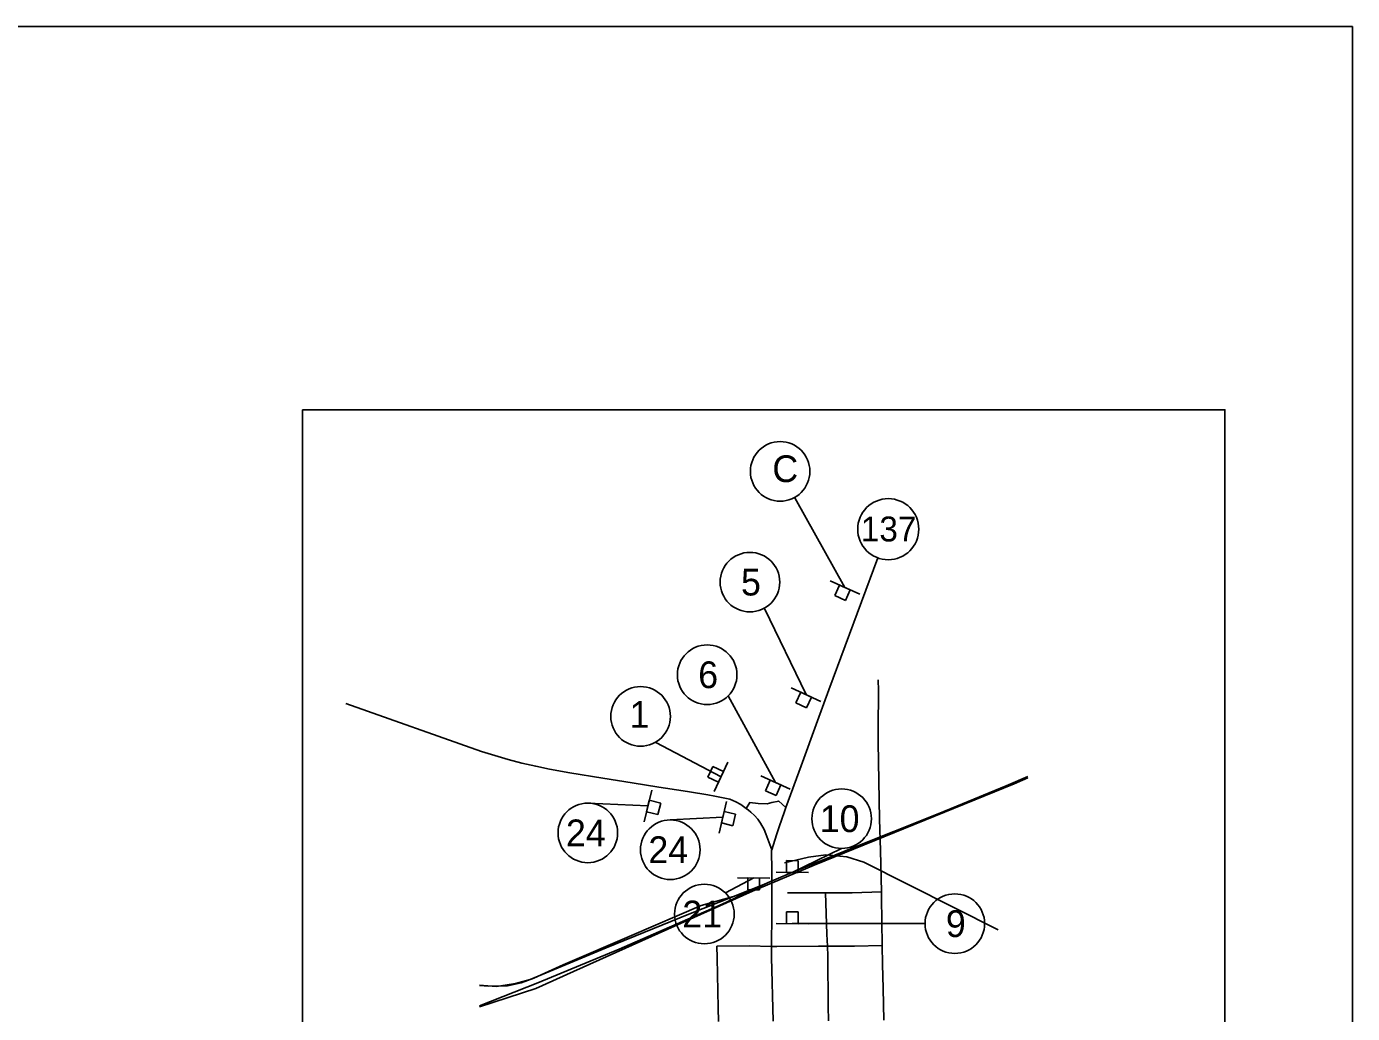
# Model space of a CAD drawing. Extents: x 10133 to 81668, y 5524 to 11018.
# Drawn here: x 15963 to 16868, y 9270 to 9944 of the extents above; entities that cross this region are included whole.
import ezdxf

# ---------------------------------------------------------------- set-up
doc = ezdxf.new("R2010")
doc.units = 0
for name, color, linetype in [('Default', 7, 'Continuous'), ('DisBoundDim', 7, 'Continuous'), ('DisCLMLOR', 7, 'Continuous'), ('DisCLMLSUR', 7, 'Continuous'), ('dsnShtPlotShapeBatchPrint', 7, 'Continuous'), ('Level 3', 7, 'Continuous'), ('trf_Signal_(Temp)_Layout', 7, 'Continuous'), ('trf_SignNumber_Text', 7, 'Continuous')]:
    doc.layers.add(name, color=color, linetype=linetype)

msp = doc.modelspace()

# ---------------------------------------------------------------- linework, layer by layer
at = {"layer": 'Default'}
for points in [[(16543.77, 9498.06), (16544.17, 9490.88), (16543.96, 9464.55), (16543.96, 9464.55)], [(16453.71, 9410.28), (16450.13, 9412.93), (16446.83, 9414.78), (16442.72, 9416.56), (16432.33, 9418.64), (16427.57, 9419.58), (16415.16, 9421.56), (16410.73, 9422.27), (16394.12, 9424.91), (16376.07, 9427.79), (16355.95, 9431.06), (16333.49, 9434.72), (16319.65, 9437.21), (16310.21, 9439.09), (16300.83, 9441.24), (16291.52, 9443.66), (16282.28, 9446.34), (16273.12, 9449.28), (16180.69, 9481.91)], [(16546.08, 9353.48), (16545.58, 9381.67), (16544.73, 9402.89), (16543.89, 9455.23), (16543.96, 9464.55)], [(16271.9, 9274.92), (16310.35, 9287.49), (16336.01, 9298.98), (16458.1, 9353.77), (16500.24, 9371.53), (16636.66, 9427.09), (16646.09, 9431.12)], [(16468.47, 9359.56), (16483.49, 9365.8), (16500.75, 9372.98), (16509.39, 9376.46), (16525.56, 9382.98), (16584.78, 9406.61), (16597.46, 9411.78), (16631.13, 9425.78), (16646.09, 9432)], [(16471.24, 9382.11), (16467.29, 9392.94), (16466.19, 9395.96), (16463.5, 9400.29), (16461.8, 9403.03), (16459.52, 9405.45), (16457.08, 9407.7), (16455.3, 9409.14), (16453.71, 9410.28)], [(16472.21, 9265.05), (16471, 9308.81), (16471.08, 9316.09), (16471.33, 9338.83), (16471.42, 9347.43), (16471.26, 9367.38), (16471.14, 9381.81), (16471.24, 9382.11)], [(16479.96, 9373.17), (16496.37, 9377.06), (16508.21, 9378.53), (16522.45, 9377.16), (16534.08, 9373.6), (16625.81, 9327.4)], [(16271.9, 9289.57), (16283.24, 9288.79), (16289.44, 9289.71), (16296.38, 9290.73), (16306.32, 9293.47), (16358.29, 9315.18), (16390.1, 9328.12), (16414.66, 9338.11), (16465.83, 9358.47), (16468.47, 9359.56)], [(16271.9, 9275.62), (16311.74, 9291.25), (16367.23, 9314.25), (16437.46, 9344.93), (16468.47, 9359.56)], [(16458.1, 9353.77), (16423.1, 9343.97), (16375.67, 9323.48), (16329.05, 9303.57), (16308.88, 9294.4), (16300.32, 9291.17), (16290.92, 9289.26), (16278.04, 9288.93), (16271.9, 9289.49)], [(16482.07, 9352.65), (16508.02, 9352.73)], [(16508.02, 9352.73), (16526.21, 9352.79), (16546.08, 9353.48)], [(16509.32, 9316.37), (16508.94, 9324.42), (16508.02, 9352.73)], [(16546.66, 9316.69), (16546.15, 9349.55), (16546.08, 9353.48)], [(16433.89, 9316.19), (16455.81, 9316.54), (16471.06, 9316.09), (16474.76, 9315.98), (16503.2, 9316.4), (16509.32, 9316.37)], [(16434.84, 9264.84), (16434.67, 9274.29), (16433.96, 9308.38), (16433.89, 9316.19)], [(16509.32, 9316.37), (16527.81, 9316.26), (16546.66, 9316.69)], [(16510.01, 9265.38), (16509.79, 9275.33), (16509.65, 9309.42), (16509.32, 9316.37)], [(16547.84, 9265.77), (16547.84, 9265.77), (16547.29, 9287.29), (16546.86, 9304), (16546.66, 9316.69)]]:
    msp.add_lwpolyline(points, dxfattribs=at)
msp.add_circle((16550.76, 9600.92), 20.85, dxfattribs=at)
at = {"layer": 'DisBoundDim'}
for p, q in [((16531.31, 9556.54), (16511.19, 9565.75)), ((16517.61, 9562.81), (16514.28, 9555.54)), ((16521.55, 9552.2), (16514.28, 9555.54)), ((16524.88, 9559.48), (16521.55, 9552.2)), ((16504.71, 9483.38), (16484.59, 9492.59)), ((16491.01, 9489.65), (16487.68, 9482.38)), ((16494.96, 9479.05), (16487.68, 9482.38)), ((16498.29, 9486.32), (16494.96, 9479.05)), ((16427.75, 9431.61), (16431.08, 9438.88)), ((16438.35, 9435.55), (16431.08, 9438.88)), ((16432.08, 9421.85), (16441.29, 9441.98)), ((16435.02, 9428.28), (16427.75, 9431.61)), ((16483.94, 9423.42), (16463.82, 9432.63)), ((16470.25, 9429.69), (16466.91, 9422.42)), ((16389.38, 9422.74), (16384.21, 9401.22)), ((16474.19, 9419.09), (16466.91, 9422.42)), ((16477.52, 9426.36), (16474.19, 9419.09)), ((16387.73, 9415.87), (16395.51, 9414)), ((16395.51, 9414), (16393.64, 9406.22)), ((16440.5, 9415.04), (16435.33, 9393.52)), ((16385.86, 9408.09), (16393.64, 9406.22)), ((16438.85, 9408.17), (16446.63, 9406.3)), ((16446.63, 9406.3), (16444.76, 9398.52)), ((16436.98, 9400.39), (16444.76, 9398.52)), ((16481.26, 9366.69), (16481.32, 9374.69)), ((16481.32, 9374.69), (16489.32, 9374.64)), ((16489.26, 9366.64), (16489.32, 9374.64)), ((16474.19, 9366.74), (16496.33, 9366.59)), ((16470.04, 9362.79), (16447.91, 9362.87)), ((16454.97, 9362.84), (16454.94, 9354.84)), ((16462.97, 9362.81), (16462.94, 9354.81)), ((16462.94, 9354.81), (16454.94, 9354.84)), ((16481.26, 9331.69), (16481.32, 9339.69)), ((16481.32, 9339.69), (16489.32, 9339.64)), ((16489.26, 9331.64), (16489.32, 9339.64)), ((16474.19, 9331.74), (16496.33, 9331.59))]:
    msp.add_line(p, q, dxfattribs=at)
at = {"layer": 'DisCLMLOR'}
for p, q in [((16514.28, 9555.54), (16517.61, 9562.81)), ((16514.28, 9555.54), (16517.61, 9562.81)), ((16514.28, 9555.54), (16517.61, 9562.81)), ((16514.28, 9555.54), (16517.61, 9562.81)), ((16521.55, 9552.2), (16514.28, 9555.54)), ((16521.55, 9552.2), (16514.28, 9555.54)), ((16521.55, 9552.2), (16514.28, 9555.54)), ((16521.55, 9552.2), (16514.28, 9555.54)), ((16517.61, 9562.81), (16524.88, 9559.48)), ((16517.61, 9562.81), (16524.88, 9559.48)), ((16517.61, 9562.81), (16524.88, 9559.48)), ((16517.61, 9562.81), (16524.88, 9559.48)), ((16524.88, 9559.48), (16521.55, 9552.2)), ((16524.88, 9559.48), (16521.55, 9552.2)), ((16524.88, 9559.48), (16521.55, 9552.2)), ((16524.88, 9559.48), (16521.55, 9552.2)), ((16487.68, 9482.38), (16491.01, 9489.65)), ((16487.68, 9482.38), (16491.01, 9489.65)), ((16487.68, 9482.38), (16491.01, 9489.65)), ((16487.68, 9482.38), (16491.01, 9489.65)), ((16494.96, 9479.05), (16487.68, 9482.38)), ((16494.96, 9479.05), (16487.68, 9482.38)), ((16494.96, 9479.05), (16487.68, 9482.38)), ((16494.96, 9479.05), (16487.68, 9482.38)), ((16491.01, 9489.65), (16498.29, 9486.32)), ((16491.01, 9489.65), (16498.29, 9486.32)), ((16491.01, 9489.65), (16498.29, 9486.32)), ((16491.01, 9489.65), (16498.29, 9486.32)), ((16498.29, 9486.32), (16494.96, 9479.05)), ((16498.29, 9486.32), (16494.96, 9479.05)), ((16498.29, 9486.32), (16494.96, 9479.05)), ((16498.29, 9486.32), (16494.96, 9479.05)), ((16427.75, 9431.61), (16431.08, 9438.88)), ((16427.75, 9431.61), (16431.08, 9438.88)), ((16427.75, 9431.61), (16431.08, 9438.88)), ((16427.75, 9431.61), (16431.08, 9438.88)), ((16431.08, 9438.88), (16438.35, 9435.55)), ((16431.08, 9438.88), (16438.35, 9435.55)), ((16431.08, 9438.88), (16438.35, 9435.55)), ((16431.08, 9438.88), (16438.35, 9435.55)), ((16435.02, 9428.28), (16427.75, 9431.61)), ((16435.02, 9428.28), (16427.75, 9431.61)), ((16435.02, 9428.28), (16427.75, 9431.61)), ((16435.02, 9428.28), (16427.75, 9431.61)), ((16438.35, 9435.55), (16435.02, 9428.28)), ((16438.35, 9435.55), (16435.02, 9428.28)), ((16438.35, 9435.55), (16435.02, 9428.28)), ((16438.35, 9435.55), (16435.02, 9428.28)), ((16466.91, 9422.42), (16470.25, 9429.69)), ((16466.91, 9422.42), (16470.25, 9429.69)), ((16466.91, 9422.42), (16470.25, 9429.69)), ((16466.91, 9422.42), (16470.25, 9429.69)), ((16470.25, 9429.69), (16477.52, 9426.36)), ((16470.25, 9429.69), (16477.52, 9426.36)), ((16470.25, 9429.69), (16477.52, 9426.36)), ((16470.25, 9429.69), (16477.52, 9426.36)), ((16474.19, 9419.09), (16466.91, 9422.42)), ((16474.19, 9419.09), (16466.91, 9422.42)), ((16474.19, 9419.09), (16466.91, 9422.42)), ((16474.19, 9419.09), (16466.91, 9422.42)), ((16477.52, 9426.36), (16474.19, 9419.09)), ((16477.52, 9426.36), (16474.19, 9419.09)), ((16477.52, 9426.36), (16474.19, 9419.09)), ((16477.52, 9426.36), (16474.19, 9419.09)), ((16385.86, 9408.09), (16387.73, 9415.87)), ((16385.86, 9408.09), (16387.73, 9415.87)), ((16385.86, 9408.09), (16387.73, 9415.87)), ((16385.86, 9408.09), (16387.73, 9415.87)), ((16387.73, 9415.87), (16395.51, 9414)), ((16387.73, 9415.87), (16395.51, 9414)), ((16387.73, 9415.87), (16395.51, 9414)), ((16387.73, 9415.87), (16395.51, 9414)), ((16395.51, 9414), (16393.64, 9406.22)), ((16395.51, 9414), (16393.64, 9406.22)), ((16395.51, 9414), (16393.64, 9406.22)), ((16395.51, 9414), (16393.64, 9406.22)), ((16393.64, 9406.22), (16385.86, 9408.09)), ((16393.64, 9406.22), (16385.86, 9408.09)), ((16393.64, 9406.22), (16385.86, 9408.09)), ((16393.64, 9406.22), (16385.86, 9408.09)), ((16436.98, 9400.39), (16438.85, 9408.17)), ((16436.98, 9400.39), (16438.85, 9408.17)), ((16436.98, 9400.39), (16438.85, 9408.17)), ((16436.98, 9400.39), (16438.85, 9408.17)), ((16438.85, 9408.17), (16446.63, 9406.3)), ((16438.85, 9408.17), (16446.63, 9406.3)), ((16438.85, 9408.17), (16446.63, 9406.3)), ((16438.85, 9408.17), (16446.63, 9406.3)), ((16446.63, 9406.3), (16444.76, 9398.52)), ((16446.63, 9406.3), (16444.76, 9398.52)), ((16446.63, 9406.3), (16444.76, 9398.52)), ((16446.63, 9406.3), (16444.76, 9398.52)), ((16444.76, 9398.52), (16436.98, 9400.39)), ((16444.76, 9398.52), (16436.98, 9400.39)), ((16444.76, 9398.52), (16436.98, 9400.39)), ((16444.76, 9398.52), (16436.98, 9400.39)), ((16481.26, 9366.69), (16481.32, 9374.69)), ((16481.26, 9366.69), (16481.32, 9374.69)), ((16481.26, 9366.69), (16481.32, 9374.69)), ((16481.26, 9366.69), (16481.32, 9374.69)), ((16481.32, 9374.69), (16489.32, 9374.64)), ((16481.32, 9374.69), (16489.32, 9374.64)), ((16481.32, 9374.69), (16489.32, 9374.64)), ((16481.32, 9374.69), (16489.32, 9374.64)), ((16489.32, 9374.64), (16489.26, 9366.64)), ((16489.32, 9374.64), (16489.26, 9366.64)), ((16489.32, 9374.64), (16489.26, 9366.64)), ((16489.32, 9374.64), (16489.26, 9366.64)), ((16489.26, 9366.64), (16481.26, 9366.69)), ((16489.26, 9366.64), (16481.26, 9366.69)), ((16489.26, 9366.64), (16481.26, 9366.69)), ((16489.26, 9366.64), (16481.26, 9366.69)), ((16454.94, 9354.84), (16454.97, 9362.84)), ((16454.94, 9354.84), (16454.97, 9362.84)), ((16454.94, 9354.84), (16454.97, 9362.84)), ((16454.94, 9354.84), (16454.97, 9362.84)), ((16454.97, 9362.84), (16462.97, 9362.81)), ((16454.97, 9362.84), (16462.97, 9362.81)), ((16454.97, 9362.84), (16462.97, 9362.81)), ((16454.97, 9362.84), (16462.97, 9362.81)), ((16462.97, 9362.81), (16462.94, 9354.81)), ((16462.97, 9362.81), (16462.94, 9354.81)), ((16462.97, 9362.81), (16462.94, 9354.81)), ((16462.97, 9362.81), (16462.94, 9354.81)), ((16462.94, 9354.81), (16454.94, 9354.84)), ((16462.94, 9354.81), (16454.94, 9354.84)), ((16462.94, 9354.81), (16454.94, 9354.84)), ((16462.94, 9354.81), (16454.94, 9354.84)), ((16481.26, 9331.69), (16481.32, 9339.69)), ((16481.26, 9331.69), (16481.32, 9339.69)), ((16481.26, 9331.69), (16481.32, 9339.69)), ((16481.26, 9331.69), (16481.32, 9339.69)), ((16481.32, 9339.69), (16489.32, 9339.64)), ((16481.32, 9339.69), (16489.32, 9339.64)), ((16481.32, 9339.69), (16489.32, 9339.64)), ((16481.32, 9339.69), (16489.32, 9339.64)), ((16489.32, 9339.64), (16489.26, 9331.64)), ((16489.32, 9339.64), (16489.26, 9331.64)), ((16489.32, 9339.64), (16489.26, 9331.64)), ((16489.32, 9339.64), (16489.26, 9331.64)), ((16489.26, 9331.64), (16481.26, 9331.69)), ((16489.26, 9331.64), (16481.26, 9331.69)), ((16489.26, 9331.64), (16481.26, 9331.69)), ((16489.26, 9331.64), (16481.26, 9331.69))]:
    msp.add_line(p, q, dxfattribs=at)
at = {"layer": 'DisCLMLSUR'}
for p, q in [((16521.25, 9561.14), (16487.03, 9622.32)), ((16494.65, 9487.99), (16466.43, 9546.73)), ((16473.88, 9428.03), (16441.58, 9487.18)), ((16436.69, 9431.91), (16392.18, 9455.3)), ((16386.79, 9411.98), (16345.78, 9413.95)), ((16437.92, 9404.28), (16402.05, 9402.45)), ((16485.26, 9366.67), (16518.96, 9382.97)), ((16458.97, 9362.83), (16439.66, 9352.6)), ((16485.26, 9331.67), (16575.86, 9331.67))]:
    msp.add_line(p, q, dxfattribs=at)
at = {"layer": 'dsnShtPlotShapeBatchPrint'}
for points in [[(16480.91, 9410.99), (16491.37, 9439.39), (16502.51, 9470.04), (16510.19, 9491.17), (16543.67, 9581.35)], [(16453.71, 9410.28), (16456.36, 9414.42), (16462.09, 9413.64), (16468.03, 9413.5), (16471.29, 9414.25), (16476.07, 9415.34), (16480.91, 9410.99)], [(16471.24, 9382.11), (16474.54, 9392.28), (16476.37, 9397.7), (16479.92, 9408.24), (16480.91, 9410.99)]]:
    msp.add_lwpolyline(points, dxfattribs=at)
at = {"layer": 'Level 3'}
msp.add_lwpolyline([(13732.52, 9944.02), (16867.53, 9944.02), (16867.53, 7924.02), (13732.52, 7924.02)], close=True, dxfattribs=at)
at = {"layer": 'trf_Signal_(Temp)_Layout'}
msp.add_lwpolyline([(16151.16, 9682.4), (16780.52, 9682.4), (16780.52, 8361.35), (16151.16, 8361.35)], close=True, dxfattribs=at)
at = {"layer": 'trf_SignNumber_Text'}
for centre in [(16476.99, 9640.37), (16456.39, 9564.78), (16427.2, 9501.55), (16381.78, 9473.14), (16518.96, 9403.3), (16345.78, 9393.62), (16402.05, 9382.12), (16425.29, 9338.23), (16596.19, 9331.67)]:
    msp.add_circle(centre, 20.33, dxfattribs=at)

# ---------------------------------------------------------------- texts
at = {"layer": 'Default'}
msp.add_text('137', height=17, dxfattribs=at).set_placement((16532.06, 9592.54))
at = {"layer": 'trf_SignNumber_Text'}
for s, height, p in [('C', 18.26, (16471.68, 9633.04)), ('5', 18.26, (16450.28, 9555.65)), ('6', 18.26, (16421.09, 9492.42)), ('1', 18.26, (16374.32, 9465.36)), ('10', 18.258, (16504.01, 9394.17)), ('24', 18.258, (16330.83, 9384.49)), ('24', 18.258, (16387.1, 9372.99)), ('21', 18.258, (16410.27, 9329.1)), ('9', 18.26, (16590.08, 9322.54))]:
    msp.add_text(s, height=height, dxfattribs=at).set_placement(p)

doc.saveas('drawing.dxf')
